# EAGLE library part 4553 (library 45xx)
3-digit BCD COUNTER
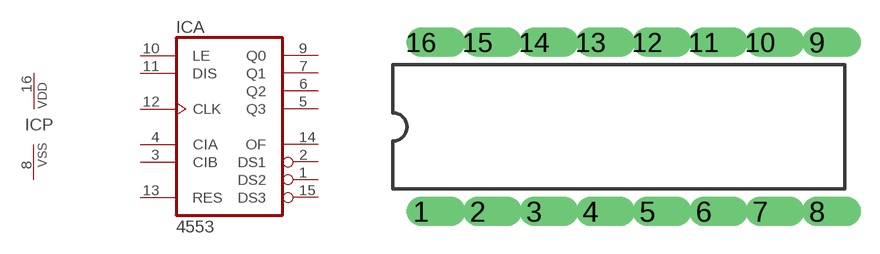
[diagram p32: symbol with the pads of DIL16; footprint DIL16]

Designator prefix IC; gates A=4553 P=PWRN

## 4553N  [DIL16]
1  A:DS2  out
2  A:DS1  out
3  A:CIB  in
4  A:CIA  in
5  A:Q3  out
6  A:Q2  out
7  A:Q1  out
8  P:VSS  pwr
9  A:Q0  out
10  A:LE  in
11  A:DIS  in
12  A:CLK  in
13  A:RES  in
14  A:OF  out
15  A:DS3  out
16  P:VDD  pwr

## Footprint DIL16 (pad centres in mm)
Dual In Line
drill 0.813 offset: 1 -8.89,-3.81; 2 -6.35,-3.81; 3 -3.81,-3.81; 4 -1.27,-3.81; 5 1.27,-3.81; 6 3.81,-3.81; 7 6.35,-3.81; 8 8.89,-3.81; 9 8.89,3.81; 10 6.35,3.81; 11 3.81,3.81; 12 1.27,3.81; 13 -1.27,3.81; 14 -3.81,3.81; 15 -6.35,3.81; 16 -8.89,3.81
